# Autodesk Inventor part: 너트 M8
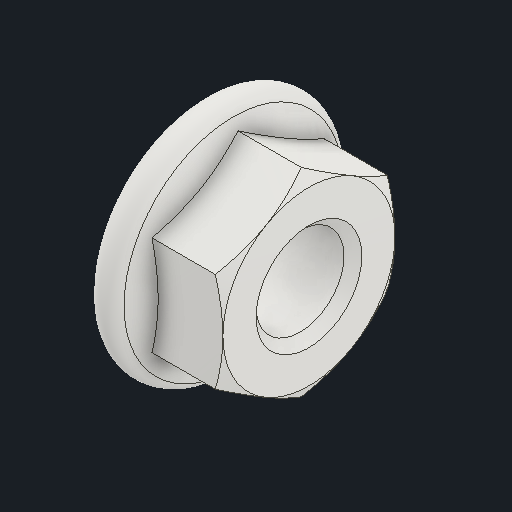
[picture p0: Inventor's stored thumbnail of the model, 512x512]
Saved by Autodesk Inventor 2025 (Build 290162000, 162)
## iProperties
Created: 2025-08
Part Number: 너트 M8
Material: 스테인리스강
Description: 플랜지붙이 6각 너트 - 일반 스레드
Document SubType Name: Modeling
Designer: infra006
Density: 8 g/cm^3
Appearance: 기본값
Author: jhkim
Sending System: Autodesk Inventor 2026
Preprocessor: ST-DEVELOPER v20.1
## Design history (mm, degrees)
feature "Solid1"
node "솔리드1"
